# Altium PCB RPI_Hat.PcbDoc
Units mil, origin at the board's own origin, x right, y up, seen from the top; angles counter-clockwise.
Board outline 2247.25 x 3072.14 mil, 4 copper layers (Top Layer, Internal Plane 1, Internal Plane 2, Bottom Layer), stack 61.88 mil thick; 71 components, 40 nets, 316 pads, 202 vias.
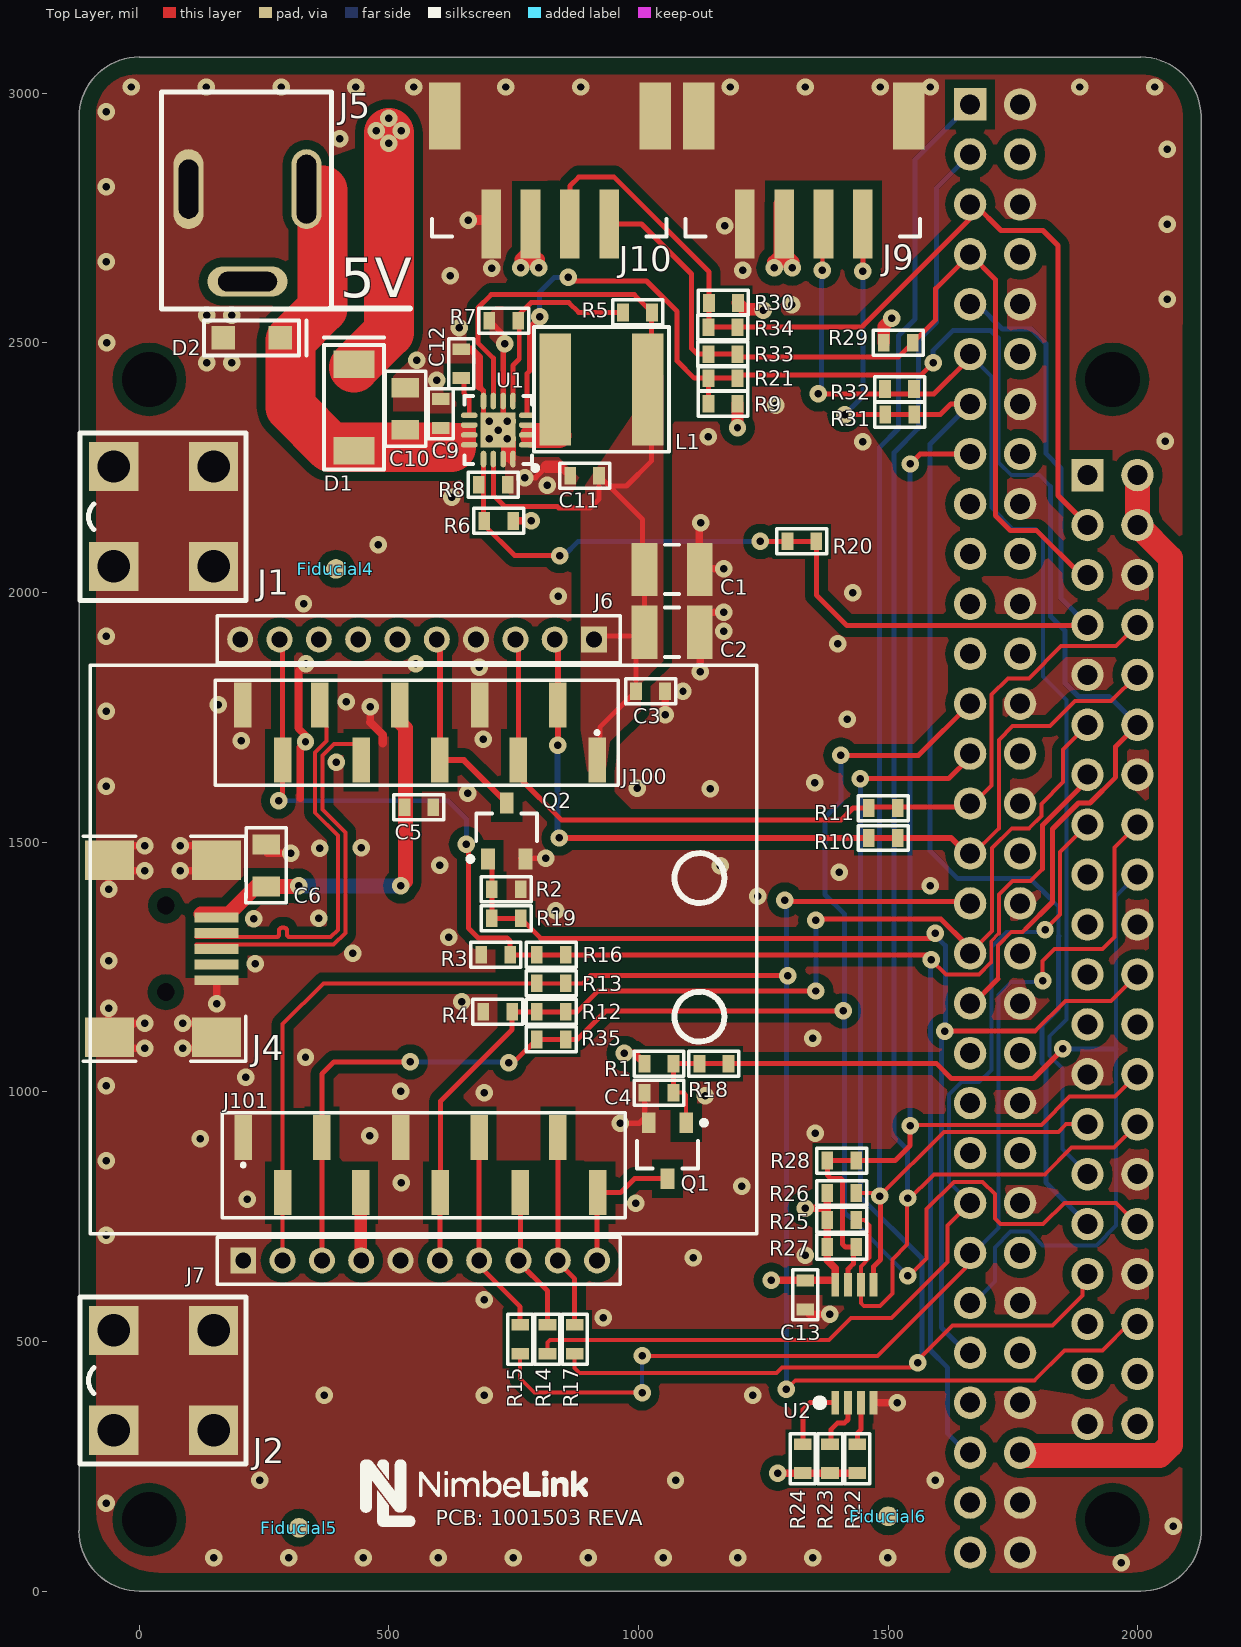
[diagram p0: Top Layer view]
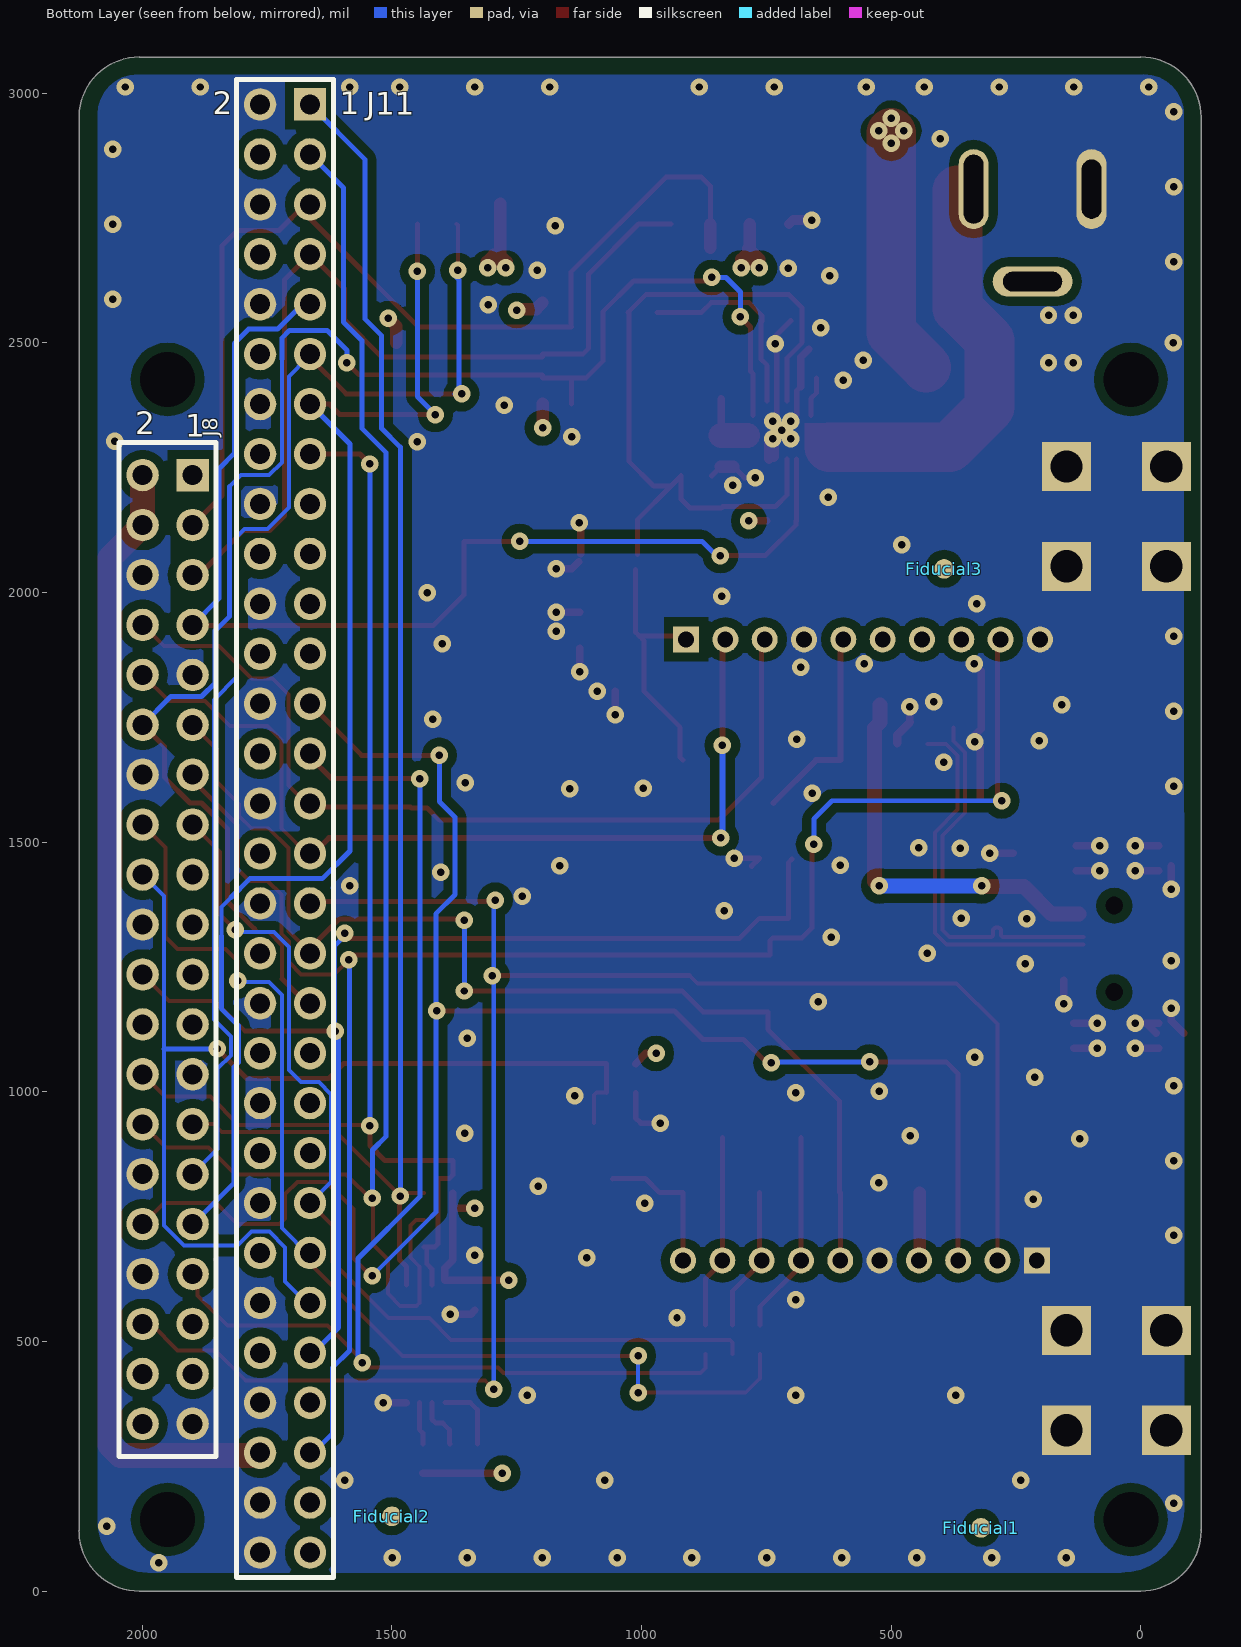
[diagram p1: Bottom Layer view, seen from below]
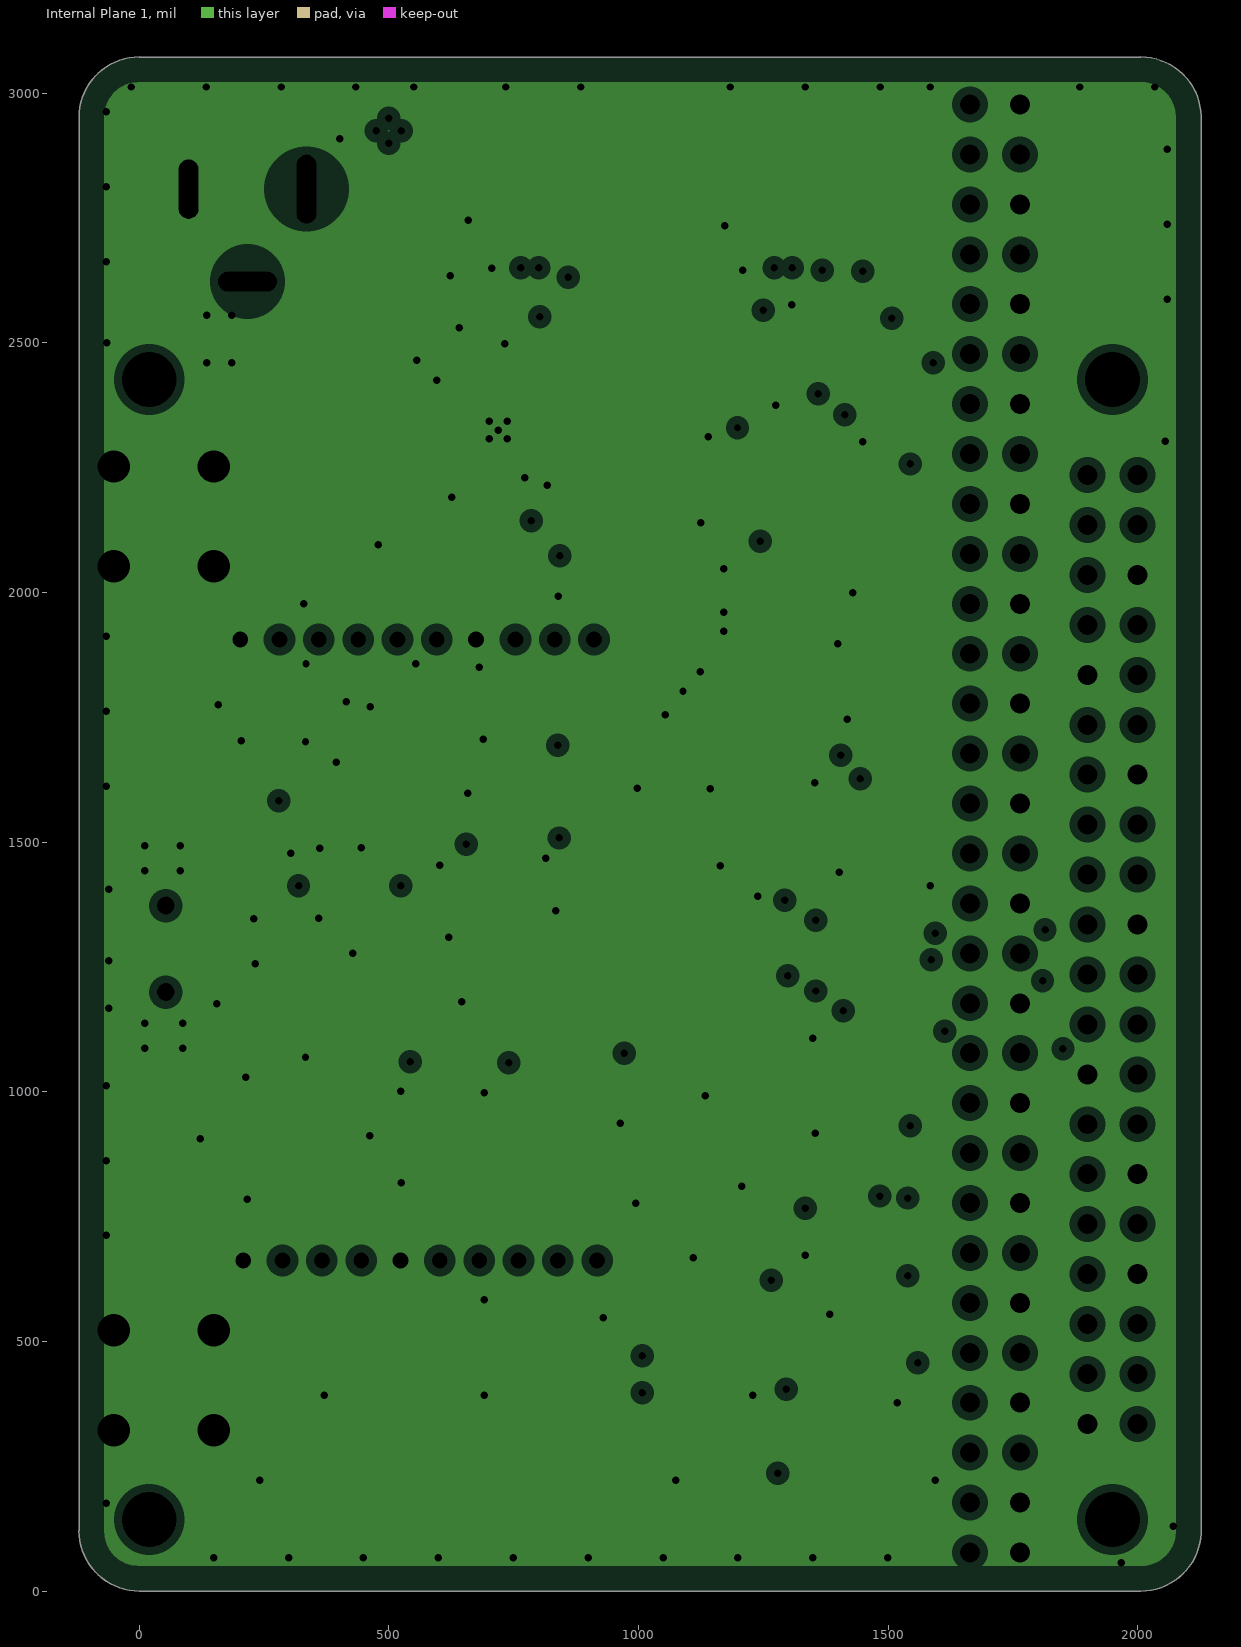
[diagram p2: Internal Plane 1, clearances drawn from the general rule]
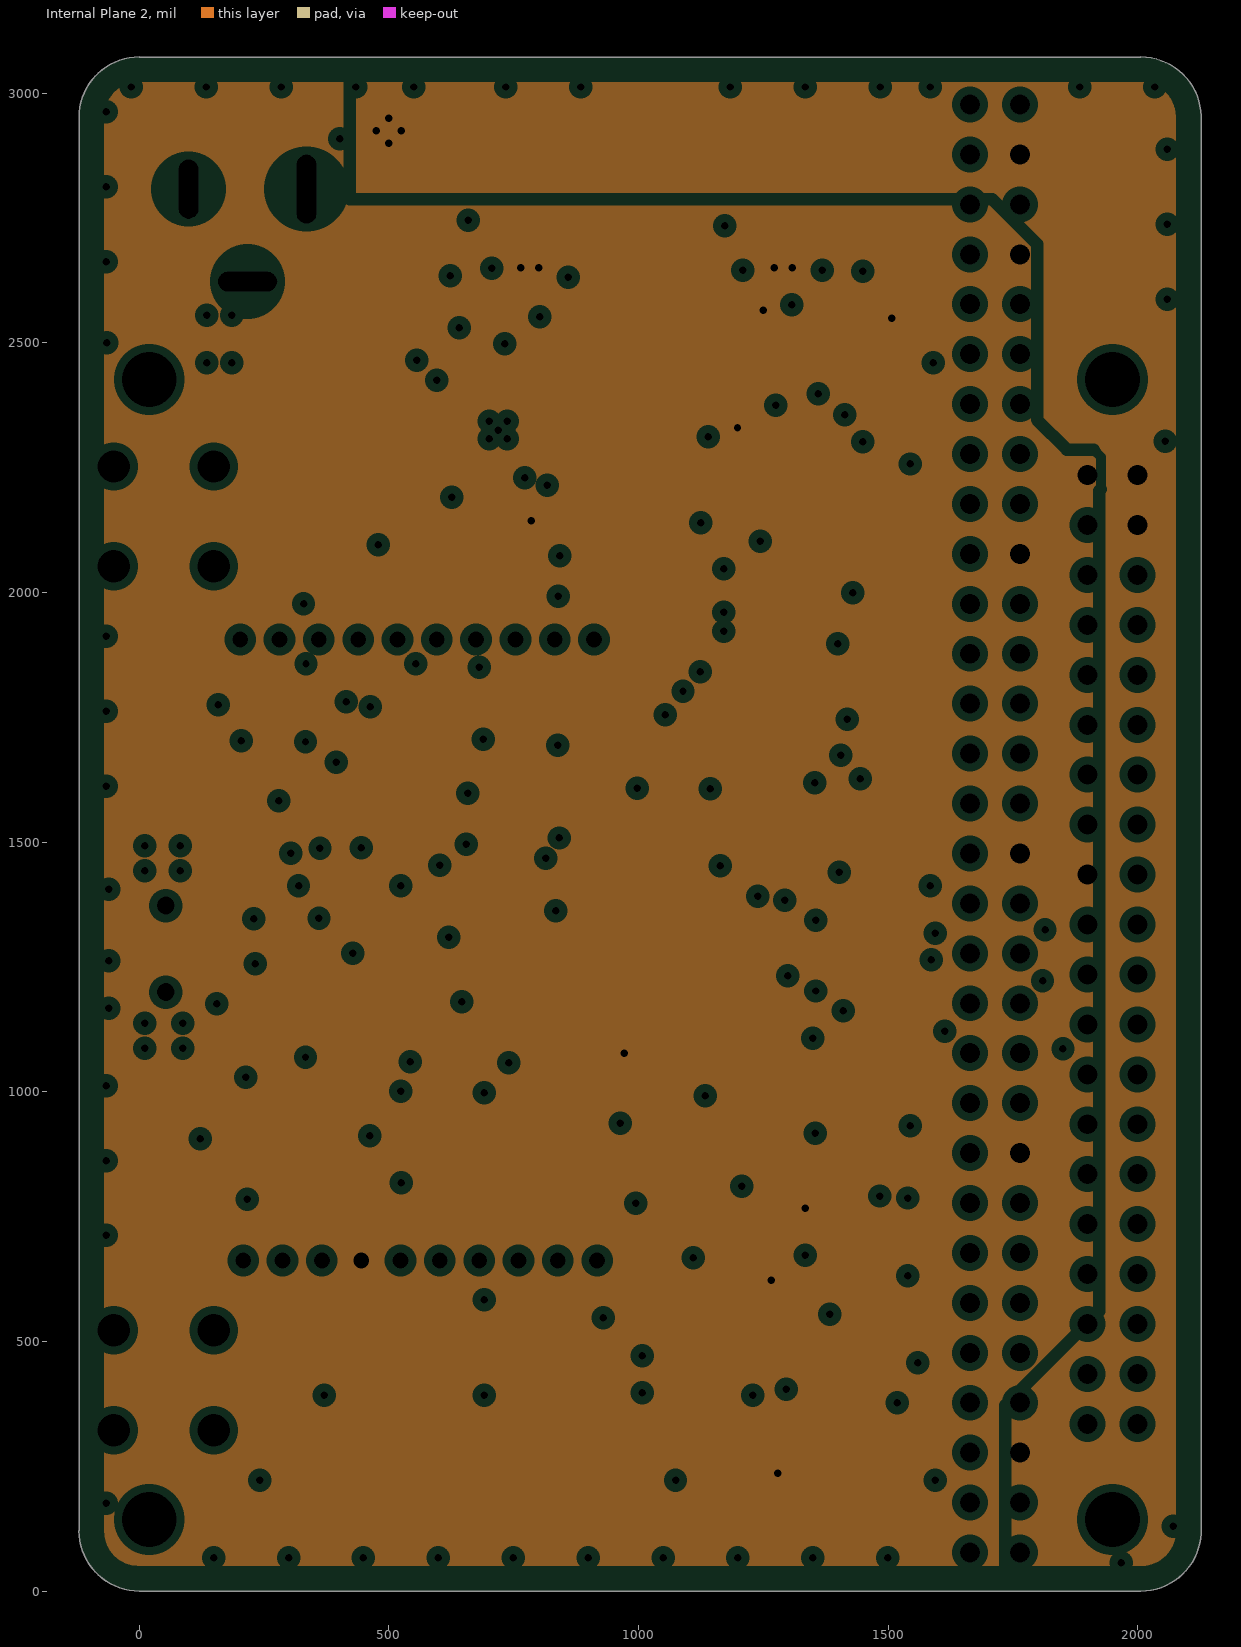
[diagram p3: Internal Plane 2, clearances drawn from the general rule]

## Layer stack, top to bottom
Top Solder: solder mask 0.4, Solder Resist, Dk 3.5
Top Layer: signal copper 1.37
Dielectric 1: core 6.7, FR-4, Dk 4.6
Internal Plane 1: plane copper 1.37, net GND
Dielectric 3: prepreg 43, Dk 4.6
Internal Plane 2: plane copper 1.37, net (Multiple Nets)
Dielectric 2: core 6.7, Dk 4.6
Bottom Layer: signal copper 1.37
Bottom Solder: solder mask 0.4, Solder Resist, Dk 3.5

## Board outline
-120.63,121 cw(c-118.11,121) -120.11,122.52 cw(c-118,123.89) -120.52,123.89 -120.52,2951.22 cw(c-118.09,2951.89) -120.61,2951.89 cw(c0.02,2951.89) 0.02,3072.51 cw(c0.02,3070) 0.76,3072.4 2005.15,3072.4 cw(c2005.89,3070) 2005.89,3072.51 cw(c2005.89,2951.89) 2126.49,2954.22 cw(c2124,2953.89) 2126.51,2953.89 2126.51,121.73 cw(c2124.11,121) 2126.63,121 cw(c2006,121) 2126.51,115.82 ccw(c2124,115.89) 2126.51,115.89 2126.51,115.82 cw(c2124,115.89) 2126.51,115.73 ccw(c2006,121) 2126.51,115.82 2126.51,115.73 cw(c2006,121) 2006,0.37 0,0.37 cw(c0,121)

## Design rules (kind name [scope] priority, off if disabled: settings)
Clearance Clearance_1 [InPolygon] p1: gap=18
Clearance [All] p2: gap=6
ComponentClearance "Skywire Model Clearance" [(HasFootprint('NPPN101BFCN-RC') OR (id='3D_STEP_Skywire'))] p1: gap=0 collisioncheckmode=3 verticalgap=0 showdistances=FALSE
ComponentClearance [All] p2: gap=7 collisioncheckmode=3 verticalgap=7 showdistances=FALSE
DiffPairsRouting [All] p1: maxlimit=30 minlimit=7 mostfreqgap=7 toplayer_minwidth=7 toplayer_maxwidth=100 toplayer_prefwidth=8 bottomlayer_minwidth=7 bottomlayer_maxwidth=100 bottomlayer_prefwidth=8 maxuncoupledlength=500
HoleSize [All] p1: absolutevalues=TRUE maxlimit=500 minlimit=15 maxpercent=80.000 minpercent=20.000
MinimumAnnularRing [All] p1: minimumring=10
MinimumSolderMaskSliver [All] p1: minsoldermaskwidth=0
PlaneClearance [All] p1: clearance=16
PlaneConnect [All] p1: planeconnectstyle=Direct reliefexpansion=20 reliefentries=4 reliefconductorwidth=20 reliefairgap=15
PolygonConnect "All Rule" [All] p1: connectstyle=Direct reliefconductorwidth=20 reliefentries=4 polygonreliefangle="90 Angle" airgapwidth=15
RoutingVias [All] p1: holewidth=15 width=35 viastyle="Through Hole" minholewidth=15 minwidth=35 maxholewidth=300 maxwidth=500
SilkToSilkClearance [All] p1: silktosilkclearance=0
SilkToSolderMaskClearance [IsPad] p1: minsilkscreentomaskgap=0 clearancetoexposedcopper=TRUE
SolderMaskExpansion SolderMaskExpansion_2 [isVia and TestpointBottom] p1: expansion=0
SolderMaskExpansion SolderMaskExpansion_1 [IsVia] p2: expansion=-10
SolderMaskExpansion [All] p3: expansion=0
UnpouredPolygon [All] p1: allowunpoured=FALSE
Width [All] p1: maxlimit=5000 minlimit=7 preferedwidth=10
21 further rules are at their usual default settings.

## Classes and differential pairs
component class TOP: C13 Fiducial1 Fiducial2 Fiducial3 Fiducial4 Fiducial5 Fiducial6 J8 J9 J10 J11 R10 R11 R12 R13 R14 R15 R16 R17 R18 R19 R20 R21 R22 R23 R24 R25 R26 R27 R28 R29 R30 R31 R32 R33 R34 R35 U2
component class Power: C9 C10 C11 C12 D1 D2 J5 L1 R5 R6 R7 R8 R9 U1
net class DIFF90: SKY_USB_N SKY_USB_P
component class Skywire: C1 C2 C3 C4 C5 C6 J1 J2 J4 J6 J7 J100 J101 Q1 Q2 R1 R2 R3 R4
differential pair SKY_USB: +SKY_USB_P -SKY_USB_N

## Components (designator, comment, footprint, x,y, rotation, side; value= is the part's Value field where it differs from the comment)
C1 "1001241" CAPC3225X25N_1210 1067,2046.42 r0 top
C2 "1001241" CAPC3225X25N_1210 1067,1920.42 r0 top
C3 "1000755" 0603 1024,1802.42 r0 top
C4 "1000755" 0603 1041,998.42 r180 top
C5 "1000755" 0603 560,1570 r0 top
C6 "1000780" 0805 254,1462.42 r90 top
C9 "1000755" 0603 604,2358.42 r90 top
C10 "1000780" 0805 533,2377 r90 top
C11 "C, 22 uF, 25V, 20%, X5R, 0603 CER" 0603 892,2234 r180 top
C12 "C, 470 pF, 50V, 5%, C0G/NP0, 0603 CER" 0603 645,2458.42 r270 top
C13 "1000755" 0603 1334,593.42 r270 top
D1 "1001261" SOD128 430,2371 r90 top
D2 "1000501" SOD123W 225,2510 r0 top
Fiducial1 "Fiducial" "Fiducial 1mm" 320,126.89 r0 bottom
Fiducial2 "Fiducial" "Fiducial 1mm" 1500,150 r0 bottom
Fiducial3 "Fiducial" "Fiducial 1mm" 394,2047.42 r90 bottom
Fiducial4 "Fiducial" "Fiducial 1mm" 394,2047.42 r90 top
Fiducial5 "Fiducial" "Fiducial 1mm" 320,126.89 r0 top
Fiducial6 "Fiducial" "Fiducial 1mm" 1500,150 r0 top
J1 "UFL to SMA" "UFL TO SMA" -51,2252.42 r270 top
J2 "UFL to SMA" "UFL TO SMA" -51,522.42 r270 top
J4 "USB MINI B" 10033526-N3212LF -177,1286.42 r270 top
J5 "1000221" PJ-202A 335,2807.89 r180 top
J6 "1000864" NPPN101BFCN-RC 910.85,1906 r270 top
J7 "1000864" NPPN101BFCN-RC 208.34,662.42 r90 top
J8 "1001252" PPPC202LFBN-RC 1899.13,2235.16 r0 bottom locked
J9 "1001260" S4B-PH-SM4-TB(LF)(SN) 1449,2738 r0 top
J10 "1001260" S4B-PH-SM4-TB(LF)(SN) 941,2738 r0 top
J11 "1001253" PPPC302LFBN-RC 1664,2977.42 r0 bottom locked
J100 "1000865" NPPN101BFLC-RC 917,1719.42 r270 top locked
J101 "1000865" NPPN101BFLC-RC 208.34,853.28 r90 top locked
L1 "1001263" NR6028 926,2407 r0 top
Q1 "1000512" SOT95P300X115-3N 1058,882 r270 top
Q2 "1000512" SOT95P300X115-3N 736,1522.42 r90 top
R1 "100K" 0603 1041,1056.42 r180 top
R2 "10K" 0603 735,1405.89 r180 top
R3 "#NAME?" 0603 714,1274.42 r0 top
R4 "#NAME?" 0603 718,1160.42 r0 top
R5 "715K" 0603 998,2561 r0 top
R6 "100K" 0603 720,2143.42 r0 top
R7 "1001234" 0603 730,2544.42 r0 top
R8 "100K" 0603 709,2216 r180 top
R9 "100K" 0603 1169.16,2378 r0 top
R10 "0" 0603 1490,1508.42 r180 top
R11 "0" 0603 1490,1568.42 r0 top
R12 "0" 0603 825,1160.42 r180 top
R13 "0" 0603 825,1217.42 r180 top
R14 "0" 0603 817.5,504.42 r270 top
R15 "0" 0603 763,504.42 r270 top
R16 "0" 0603 825,1274.42 r180 top
R17 "0" 0603 872,504.42 r270 top
R18 "0" 0603 1151,1056.42 r180 top
R19 "0" 0603 735,1347.42 r180 top
R20 "0" 0603 1327,2102.42 r180 top
R21 "0" 0603 1169.16,2429.42 r0 top
R22 "#NAME?" 0603 1438,265.42 r270 top
R23 "#NAME?" 0603 1383.5,265.42 r270 top
R24 "#NAME?" 0603 1329,265.42 r270 top
R25 "1000803" 0603 1407,743.42 r180 top
R26 "1000803" 0603 1407,797.42 r180 top
R27 "#NAME?" 0603 1407,689.42 r180 top
R28 "0" 0603 1407,862.42 r0 top
R29 "1000803" 0603 1520,2500 r180 top
R30 "1000803" 0603 1170,2580 r0 top
R31 "0" 0603 1523,2356.42 r0 top
R32 "0" 0603 1522.84,2407.44 r0 top
R33 "0" 0603 1169,2477.42 r180 top
R34 "0" 0603 1169,2531.42 r180 top
R35 "0" 0603 825,1105 r180 top
U1 "TPS62130RGTT" QFN50P300X300X100_HS-17N 719,2325.42 r180 top
U2 "." "TSSOP8 4.4x3 CASE 948AL-01" 1394,377.42 r90 top

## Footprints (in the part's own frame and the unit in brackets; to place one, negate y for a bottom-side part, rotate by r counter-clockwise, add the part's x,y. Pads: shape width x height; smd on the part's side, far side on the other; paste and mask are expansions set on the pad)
0603 [mm]
  rect 0.6x0.9 smd: 1(-0.737,0) 2(0.737,0)
  silkscreen extent -1.27,-0.64 1.27,0.64, body extent -0.8,-0.38 0.8,0.42, height 0.45
0805 [mm]
  rect 1x1.4 smd: 1(-1.3,0) 2(0.838,0)
  silkscreen extent -2.12,-1.03 1.69,1.02, body extent -1.21,-0.6 0.79,0.65, height 0.5
10033526-N3212LF [mm]
  rect 0x0 hole 0.9 unplated: 0(-2.2,5.85) 0(2.2,5.85)
  rect 0.5x2.25 smd: 1(-1.6,8.43) 2(-0.8,8.43) 3(0,8.43) 4(0.8,8.43) 5(1.6,8.43)
  rect 2x2.5 smd: 6(-4.5,8.43) 6(-4.5,2.98) 6(4.5,8.43) 6(4.5,2.98)
  silkscreen extent -5.72,1.65 5.71,9.91, body extent -4.95,0 4.95,9.4, height 4.05
CAPC3225X25N_1210 [mm] "Chip Capacitor, 2-Leads, 1210"
  rect 1.3x2.7 smd: 1(-1.4,0) 2(1.4,0)
  silkscreen extent -0.35,-1.25 0.35,1.25, body extent -1.7,-1.35 1.7,1.35, height 2.5
"Fiducial 1mm" [mm]
  round 1 smd paste-0.5: Fiducial(0,0)
NPPN101BFCN-RC [mil]
  rect 52x52 hole 31.5: 1(0,0)
  round 52 hole 31.5: 2(0,-78.74) 3(0,-157.48) 4(0,-236.22) 5(0,-314.96) 6(0,-393.7) 7(0,-472.44) 8(0,-551.18) 9(0,-629.92) 10(0,-708.66)
  silkscreen extent -48,-755 47,52
NPPN101BFLC-RC [mm] "Skywire Footprint with surfacemount pads"
  rect 2.29x0.89 smd: 1(1.4,0) 2(-1.4,-2) 3(1.4,-4) 4(-1.4,-5.969) 5(1.4,-8) 6(-1.4,-10.033) 7(1.4,-12) 8(-1.4,-14.097) 9(1.4,-16) 10(-1.4,-18.034)
  silkscreen extent -2.67,-19.43 2.67,1.07, body extent -2.14,-19.43 2.31,1.07, height 4.5
NR6028 [mm]
  rect 1.6x5.7 smd: 1(-2.35,0) 2(2.35,0)
  silkscreen extent -3.43,-3.17 3.43,3.17, body extent -3.05,-3.05 3.05,3.05, height 2.8
PJ-202A [mil] "PJ-202A  Barrel Plug"
  oval 60x160 hole 39.37 slot 137.8 at 90 deg: 1(0,0)
  oval 160x60 hole 39.37 slot 118.11 at 0 deg: 2(118.11,185.04)
  oval 60x160 hole 39.37 slot 118.11 at 90 deg: 3(236.22,0)
  silkscreen extent -50,-195 290,240, body extent -28,-180 538,190, height 433
PPPC202LFBN-RC [mil]
  rect 65x65 hole 40: 1(0,0)
  round 65 hole 40: 2(100,0) 3(0,100) 4(100,100) 5(0,200) 6(100,200) 7(0,300) 8(100,300) 9(0,400) 10(100,400) 11(0,500) 12(100,500) 13(0,600) 14(100,600) 15(0,700) 16(100,700) 17(0,800) 18(100,800) 19(0,900) 20(100,900) 21(0,1000) 22(100,1000) 23(0,1100) 24(100,1100) 25(0,1200) 26(100,1200) 27(0,1300) 28(100,1300) 29(0,1400) 30(100,1400) 31(0,1500) 32(100,1500) 33(0,1600) 34(100,1600) 35(0,1700) 36(100,1700) 37(0,1800) 38(100,1800) 39(0,1900) 40(100,1900)
  silkscreen extent -47,-65 147,1965, body extent -51,-60 149,1960, height 335
PPPC302LFBN-RC [mil]
  rect 65x65 hole 40: 1(0,0)
  round 65 hole 40: 2(100,0) 3(0,100) 4(100,100) 5(0,200) 6(100,200) 7(0,300) 8(100,300) 9(0,400) 10(100,400) 11(0,500) 12(100,500) 13(0,600) 14(100,600) 15(0,700) 16(100,700) 17(0,800) 18(100,800) 19(0,900) 20(100,900) 21(0,1000) 22(100,1000) 23(0,1100) 24(100,1100) 25(0,1200) 26(100,1200) 27(0,1300) 28(100,1300) 29(0,1400) 30(100,1400) 31(0,1500) 32(100,1500) 33(0,1600) 34(100,1600) 35(0,1700) 36(100,1700) 37(0,1800) 38(100,1800) 39(0,1900) 40(100,1900) 41(0,2000) 42(100,2000) 43(0,2100) 44(100,2100) 45(0,2200) 46(100,2200) 47(0,2300) 48(100,2300) 49(0,2400) 50(100,2400) 51(0,2500) 52(100,2500) 53(0,2600) 54(100,2600) 55(0,2700) 56(100,2700) 57(0,2800) 58(100,2800) 59(0,2900) 60(100,2900)
  silkscreen extent -47,-50 147,2950, body extent -50,-60 150,2960, height 335
QFN50P300X300X100_HS-17N [mm] "QFN, 16-Leads, Body 3.00x3.00mm, Pitch 0.50mm, Thermal Pad 1.78x1.78mm, IPC Medium Density"
  oval 0.85x0.28 smd: 1(-1.475,0.75) 2(-1.475,0.25) 3(-1.475,-0.25) 4(-1.475,-0.75) 9(1.475,-0.75) 10(1.475,-0.25) 11(1.475,0.25) 12(1.475,0.75)
  oval 0.28x0.85 smd: 5(-0.75,-1.475) 6(-0.25,-1.475) 7(0.25,-1.475) 8(0.75,-1.475) 13(0.75,1.475) 14(0.25,1.475) 15(-0.25,1.475) 16(-0.75,1.475)
  rect 1.78x1.78 smd paste-0.8: 17(0,0)
  silkscreen extent -2,-1.73 1.73,2.06, body extent -1.58,-1.57 1.57,1.58, height 1
S4B-PH-SM4-TB(LF)(SN) [mm]
  rect 1x3.5 smd: 1(-6,0) 2(-4,0) 3(-2,0) 4(0,0)
  rect 1.6x3.4 smd: 5(-8.35,5.5) 5(2.35,5.5)
  silkscreen extent -9.02,-0.64 2.92,0.25, body extent -9,-1.52 2.9,7.08, height 5.6
SOD123W [mm]
  rect 1.2x1.2 smd: A(-1.45,0) K(1.45,0)
  silkscreen extent -2.41,-0.89 2.79,0.89, body extent -1.4,-0.95 1.4,0.95, height 2.5
SOD128 [mm]
  rect 1.4x2.1 smd: A(-2.2,0) K(2.2,0)
  silkscreen extent -3.17,-1.52 3.56,1.52, body extent -2.03,-1.33 1.91,1.4, height 2.5
SOT95P300X115-3N [mm] "SOT23, 3-Leads, Body 3.10x3.00mm, Pitch 0.95mm, IPC Medium Density"
  rect 1.05x0.7 smd: 1(-1.425,0.95) 2(-1.425,-0.95) 3(1.425,0)
  silkscreen extent -1.55,-1.55 0.9,1.98, body extent -0.9,-1.55 0.9,1.55, height 1.15
"TSSOP8 4.4x3 CASE 948AL-01" [mm]
  rect 1.2x0.4 smd: 1(0,0) 2(0,-0.65) 3(0,-1.3) 4(0,-1.95) 5(6,-1.95) 6(6,-1.3) 7(6,-0.65) 8(6,0)
  silkscreen extent -0.05,0.74 0.05,0.84, body extent -0.35,-2.46 6.25,0.59, height 1.2
"UFL TO SMA" [mm]
  rect 2.5x2.5 hole 1.651: 1(0,5.08) 1(0,0) 1(5.08,5.08) 1(5.08,0)
  silkscreen extent -1.7,-1.71 6.81,6.73, body extent -1.02,-10.03 5.97,22.61, height 9.44

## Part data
C1 C2: "Capacitor. 100uF, 10V, 20%, X5R, 1210"
C3 C4 C5 C9 C13: "Capacitor, 0.1 uF, 16V, 5%, X7R, 0603"
C6 C10: "Capacitor, 10 uF, 25V, 10%, X5R, 0805"
C11: library part 1000932, "Capacitor, 22 uF, 25V, 20%, X5R, 0603"
C12: library part 1000777, "Capacitor, 470 pF, 50V, 5%, C0G/NP0, 0603"
D1: "Diode, Schottky, 30V, 3A, 0.360 Vf, SOD-128"
D2: "Diode, TVS, Unidirectional, 5V, 43.5A, SOD-123W"
Fiducial1 Fiducial2 Fiducial3 Fiducial4 Fiducial5 Fiducial6: "Fiducial, 1mm"
J1 J2: library part 1000732, "Connector, ANT, UFL to PCB Mount SMA, UFL Down, 53mm, TH"
J4: library part 1000127, "Connector, USB, Mini B, Right Angle, SMD"
J5: "Connector, Barrel, 24V, 2.5A, 2.1mm ID, 5.5mm OD"
J6 J7: "Connector, Header, Female, 2.00mm, 10x1, TH"
J8: "Connector, Header, Female, 2.54mm, 20x2, TH"
J9 J10: "Connector, Header, Male, 2.00mm, 4x1, Right Angle, SMD"
J11: "Connector, Header, Female, 2.54mm, 30x2, TH"
J100 J101: "Connector, Female, 2.00mm, 10x1, SMD, Left Oriented"
L1: "Inductor, 2.2uH, 3.7A, 30%, 26mOhm, 6.00x6.00mm"
Q1 Q2: "Transistor, MOSFET, N-CH, 25V, 0.220mA, SOT-23-3"
R1 R6 R8 R9: library part 1000799, "Resistor, 100K, 1%, 1/10W, 0603"
R2: library part 1000591, "Resistor, 10K, 1%, 1/10W, 0603"
R3 R4 R22 R23 R24 R27: library part 1000590, "Resistor, 1K, 1%, 1/10W, 0603"
R5: library part 1000656, "Resistor, 715K, 1%, 1/10W, 0603"
R7: "Resistor, 180K, 1%, 1/10W, 0603"
R10 R11 R12 R13 R14 R15 R16 R17 R18 R19 R20 R21 R28 R31 R32 R33 R34 R35: library part 1000666, "Resistor, 0, 1/10W, 0603"
R25 R26 R29 R30: "Resistor, 4.7K, 1%, 1/10W, 0603"
U1: library part 1001036, "IC, Buck, ADJ, 3V-17V , 3A, QFN"
U2: library part 1001385, "IC, EEPROM, I2C, 32Kb, 400KHz, 1.7V-5.5V, 8-TSSOP"

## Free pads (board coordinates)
  round 0 hole 110 unplated: 0(20,143.42) 0(20,2426.89) 0(1949.13,143.42) 0(1949.13,2426.89)
  rect 20x20 on Mech1: 0(1899.13,2235.16)
  round 50 on Mech1: 1(1999.13,2235.16)
  round 50 on Drill Drawing: 1(1999.13,2235.16)

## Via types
v1: diameter 35, hole 15, Top Layer to Bottom Layer, 202 vias

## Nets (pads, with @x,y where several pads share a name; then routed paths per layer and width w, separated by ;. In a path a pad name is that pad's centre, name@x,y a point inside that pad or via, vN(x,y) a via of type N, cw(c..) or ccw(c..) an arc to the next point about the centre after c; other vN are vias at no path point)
EEPROM_SCL: J8.28 J11.3 R25.1 U2.6 | length 3156.9
  Top Layer w8: R25.1 1452,743.42 1463,732.42 1463,668.42 1445.18,650.61 U2.6 1445.18,577.24 1451,571.42 1483.63,571.42 1508.1,595.9 1508.1,664.1 1538,694 1538,781.42 1591.5,834.92 1813.5,834.92 1867,888.42 1952.4,888.42 J8.28
  Bottom Layer w10: v1(1539,787.42) 1539,883.5 1511.5,911 1511.5,2280 1560.25,2328.75 1560.25,2504.75 1597,2541.5 1597,2810.42 J11.3
EEPROM_SDA: J8.27 J11.1 R26.1 U2.5 | length 2968.5
  Top Layer w8: R26.1 1470,797.42 v1@1485,782.42 ; v1(1483,791.42) 1611.5,919.92 1840.72,919.92 1855.95,935.16 J8.27
  Top Layer w10: U2.5 1470.77,650.2 1485,664.42 v1@1485,782.42
  Bottom Layer w10: v1@1483,789.42 v1(1483,791.42) 1483,2291 1520.5,2328.5 1520.5,2514.5 1553.5,2547.5 1553.5,2866.92 J11.1
GND: C1.2 C2.2 C3.2 C4.2 C5.2 C6.2 C9.2 C10.2 C11.2 C12.1 C13.2 D2.A J1.1 J2.1 J4.5 J4.6 J5.3 J6.4 J6.10 J7.1 J7.5 J8.6 J8.9 J8.14 J8.20 J8.25 J8.30 J8.34 J8.39 J9.1 J9.5 J10.1 J10.5 J11.2 J11.6 J11.10 J11.14 J11.18 J11.22 J11.26 J11.30 J11.34 J11.38 J11.42 J11.46 J11.50 J11.54 J11.58 J11.60 J100.4 J100.10 J101.1 J101.5 Q1.2 Q2.2 R2.1 R3.1 R4.1 R7.1 R8.1 U1.6 U1.8 U1.15 U1.16 U1.17 U2.4 | length 2095.1
  Top Layer w11: 681.22,2412.21 689.47,2403.95 U1.8 U1.17@689.47,2354.95 ; R7.1 728.84,2516.58 U1.6 U1.17@728.84,2343.42 ; v1(772,2230) 794,2230 816,2252 ; Q2.2@779.4,1452.29 764.27,1467.42 v1(814,1467.42) ; 841,2252 C11.2@859,2234 ; v1(963,937.42) 1001.5,937.42 1012,947.93 C4.2
  Top Layer w15: J4.6@-86,1117.42 -61,1142.42 v1(-61,1167.42) ; v1(-61,1405.42) J4.6@-61,1452.42 ; J4.6@-36,1087.42 v1(11,1087.42) ; J4.6@-36,1137.42 v1(11,1137.42) ; J4.6@-36,1442.42 v1(11,1442.42) ; J4.6@-36,1492.42 v1(11,1492.42) ; J4.6@-31,1117.42 J4.6@-11,1137.42 ; v1(82,1442.42) J4.6@129,1442.42 ; v1(82,1492.42) J4.6@129,1492.42 ; v1(87,1087.42) J4.6@134,1087.42 ; v1(87,1137.42) J4.6@134,1137.42 ; v1(154.89,1176.43) J4.5 ; C6.2@256,1477.42 v1(303,1477.42) ; 322,1588 322,1690 v1(333,1701) 333,1713.86 319.48,1727.38 319.48,1842.9 v1(334,1857.42) ; 463,1740 v1(463,1771) ; 665,2487.42 681.22,2471.21 681.22,2412.21 ; v1(1053,1755.42) C3.2 ; C1.2@1122,2077.42 v1@1122,2124.42 ; v1(1124,1841.42) C2.2@1124,1888.42 ; C2.2@1124,1960.42 v1(1171,1960.42) ; C1.2@1126,2061.42 1140,2047.42 v1@1174,2047.42 ; C13.2@1334,562.42 1341.42,555 v1(1383,555) ; U2.4 v1(1517.77,377.42)
  Top Layer w17: 463,1740 488,1715 488,1698
  Top Layer w20: v1(659,2746) 696.78,2746 J10.1 ; v1(719,2325.42) U1.17@737,2307.42 ; U1.15@734.34,2271.54 U1.17@734.34,2300.09 ; U1.17@736,2304.42 740,2304.42 744.34,2300.09 U1.16@744.34,2267.35
  Top Layer w25: 816,2252 841,2252
  other v1: 1967,57.42 149,67.42 299,67.42 449,67.42 599,67.42 749,67.42 899,67.42 1049,67.42 1199,67.42 1349,67.42 1499,67.42 2071,130.42 -66,176.42 241,222.42 1074,222.42 1594,222.42 371,392.42 691,392.42 1229,392.42 929,547.42 691,584 1110,668 1334,672.42 -66,712.42 994,777 216,785 1207,811.42 525,818 -66,862.42 122,906 462,912 1354,917.42 1134,992.42 691,998 524,1001 -66,1012.42 213,1029 333,1069 1349,1107 646,1180.42 232,1257 -61,1262.42 428,1278 620,1310 229,1347 360,1348 834,1362.42 1239,1392 1584,1412.42 1402,1440 1164,1452.42 602,1454 362,1488 445,1489 658,1598 1144,1607.42 997,1608 -66,1612.42 1353,1619 395,1660 204,1703 689,1706 1418,1746 -66,1762.42 158,1775 415,1781 1089,1802.42 681,1850 554,1857.42 1399,1897 -66,1912.42 1171,1922.42 329,1977.42 839,1992.42 1429,2000 1171,2047.42 479,2096 1125,2140 626,2191 817,2215 1449,2302.42 2055,2303 701,2307.92 737,2307.92 1140,2312 701.16,2343.26 737,2343.42 1275,2375 596,2425 135,2460 185,2460 556,2465 732,2498 -65,2500.42 641,2530 135,2555 185,2555 1307,2576 2059,2587.42 623,2634 1209,2645 706,2649 -66,2662.42 1173,2735 2059,2737.42 -66,2812.42 2059,2887.42 402,2909 -66,2962.42 -16,3012.42 134,3012.42 284,3012.42 434,3012.42 550,3012.42 734,3012.42 884,3012.42 1184,3012.42 1334,3012.42 1484,3012.42 1584,3012.42 1884,3012.42 2034,3012.42
GPIO4: J8.7 J11.9 R6.1 R8.2 R20.1 R20.2 U1.13 | length 2293.9
  Top Layer w10: R6.1@689.47,2143.42 U1.13 ; R6.1 691,2135 752,2074 v1(842,2074) ; v1(1244,2102.42) R20.2 R20.1 1356,1995 1417.08,1933.92 1899.13,1933.92 J8.7
  Bottom Layer w10: v1(842,2074) 850.58,2074 879,2102.42 v1(1244,2102.42) ; J11.9 1679,2577.42 1729,2527.42 1787,2527.42 1815.63,2498.79 1815.63,2278.84 1846,2248.47 1846,1988.29 J8.7
GPIO5: J8.29 J9.3 J11.11 R32.1 R32.2 | length 2487.5
  Top Layer w8: v1(1368,2645) 1368,2735.74 J9.3
  Top Layer w10: v1(1360,2398) 1591.58,2398 J11.11@1664,2470.42
  Bottom Layer w8: J11.11 1669.71,2471.71 1669.71,2469.5 1706.5,2432.71 1706.5,2169.92 1749,2127.42 1795,2127.42 1810,2112.42 1810,1831.42 1856.63,1784.79 1856.63,1144.63 1822.5,1110.5 1822.5,1073 1849,1046.5 1849,885.29 J8.29
  Bottom Layer w10: v1(1360,2398) 1374,2398 1366,2406 1366,2627 v1@1379,2640
GPIO6: J8.31 J9.4 J11.13 R31.1 R31.2 | length 2575.4
  Top Layer w10: v1(1413,2356.42) R31.1 R31.2 1604.42,2356.42 1625.42,2377.42 J11.13 ; v1(1449,2643) J9.4
  Bottom Layer w8: 1822.21,1389.21 1841.5,1369.92 1841.5,1312.19
  Bottom Layer w10: v1(1413,2356.42) 1449,2392.42 v1(1449,2643) ; J11.13 1584,2297.42 1584,1482.42 1639.5,1426.92 1784.5,1426.92 1822.21,1389.21 ; 1841.63,1312.33 1841.5,1312.19 1841.5,1166.5 1807.5,1132.5 1807.5,1058.4 1816,1049.9 1816,818.29 J8.31
GPIO7: J8.26 J11.15 R27.1 R28.1 R28.2 U2.7 | length 2474.1
  Top Layer w8: v1(1544,932.42) 1545.5,933.92 1807,933.92 1863.5,990.42 1954.4,990.42 J8.26
  Top Layer w10: U2.7 1419.59,645.01 1430.18,655.61 R27.1@1430.18,689.42 ; R27.1 R27.1@1430.18,689.42 ; v1(1544,932.42) 1544,892.42 1514,862.42 R28.2 R28.1 1378,833.42 1385.28,826.14 1405.28,826.14 1408,823.42 1408,695.42 1414,689.42 R27.1@1430.18,689.42 ; v1(1544,2257.42) 1564,2277.42 1657,2277.42 J11.15@1664,2270.42
  Bottom Layer w10: v1(1544,932.42) v1(1544,2257.42)
GPIO12: J7.3 J8.32 J11.25 J101.3 R35.1 R35.2 | length 3599.5
  Top Layer w8: v1@1533,634 1545,634 1577,666 1577,765 1631.92,819.92 1689.08,819.92 1714,795 1714,746 1725.08,734.92 1809.92,734.92 1852.66,777.66 1956.63,777.66 J8.32
  Top Layer w10: J7.3@365.82,659.42 365.82,821 J101.3 365.82,1035.82 390,1060 v1(543,1060) ; v1(740,1058) 749,1058 R35.2 R35.1 877,1105 934,1162 v1(1410,1162) ; v1(1405,1674) 1560.58,1674 J11.25
  Bottom Layer w8: 1420,751 v1(1539,632)
  Bottom Layer w10: v1(543,1060) v1@740,1060 ; v1(1405,1674) 1405,1581.5 1373.5,1550 1373.5,1395.03 1412,1356.53 1412,759 1420,751
GPIO13: J8.33 J11.27 R17.2 | length 2623.2
  Top Layer w8: R17.2 872,447.42 882,437.42 1276.42,437.42 1287.42,448.42 1545,448.42 1629,532.42 1829,532.42 1889,592.42 1889,625.02 J8.33
  Top Layer w10: v1(1444,1627.42) 1621,1627.42 J11.27@1664,1670.42
  Bottom Layer w10: v1(1444,1627.42) 1444,790.12 1568,666.12 1568,466.42 v1(1559,457.42)
GPIO18: J8.12 J11.37 R9.1 R21.1 R21.2 U1.4 | length 3134
  Top Layer w8: 1720,1226.42 1720,1293.53 1746.4,1319.92 1768.62,1319.92 1775.62,1326.92
  Top Layer w10: U1.4 777.07,2439 781.81,2443.74 781.81,2531.81 v1(802,2552) ; v1(859,2631) 866,2624 1016,2624 1077,2563 1077,2464 1111.58,2429.42 R21.1 ; R9.1 R21.1 ; v1(1590,2460) 1566.15,2436.15 1471.26,2436.15 1471.03,2435.92 1198.16,2435.92 R21.2 R21.1 ; J11.37@1664,1170.42 1720,1226.42 ; 1775.62,1326.92 1829,1380.3 1829,1526.54 1881.12,1578.66 1904.15,1578.66 1955.63,1630.14 1955.63,1691.66 J8.12
  Bottom Layer w8: 1720.5,2468 1720.5,2260.82 1746.4,2234.92 1802.5,2234.92 1825,2212.42
  Bottom Layer w10: v1(802,2552) 802,2602 831,2631 v1(859,2631) ; v1(1590,2460) 1590,2485 1630,2525 1705,2525 1720.5,2509.5 1720.5,2468 ; 1825,2212.42 1825,1952.49 1854,1923.49 1854,1818.77 1881.12,1791.66 1942.63,1791.66 J8.12
GPIO22: J8.15 J11.45 R14.2 | length 1977.9
  Top Layer w8: R14.2 817.5,497.92 823,503.42 1381.42,503.42 1425,547 1507,547 1619,659 1619,732.42 J11.45 ; v1(1814,1325) 1844,1355 1844,1480.02 J8.15
  Bottom Layer w8: J11.45@1664,770.42 J11.45@1667.5,773.92 ; J11.45 1621.5,819.92 1621.5,995.03 1646.4,1019.92 1682.2,1019.92 1706.5,1044.22 1706.5,1289.92 1736.5,1319.92 v1@1807.5,1319.92
GPIO23: J8.16 J11.47 R15.2 | length 2221.8
  Top Layer w8: R15.2 763,426.42 792,397.42 v1(1007,397.42) ; v1(1007,471.42) 1478.8,471.42 1664,656.63 J11.47@1664,670.42 ; v1(1809,1222.42) 1809,1262.42 1832.79,1286.21 1929.21,1286.21 1953.49,1310.49 1953.49,1489.51 J8.16
  Bottom Layer w8: v1(1007,397.42) v1(1007,471.42) ; J11.47@1664,670.42 1720.5,726.92 1720.5,1194.03 1746.4,1219.92 1806.5,1219.92 v1(1809,1222.42)
GPIO24: C4.1 J8.18 J11.49 Q1.1 R1.1 R18.1 R18.2 | length 2206.8
  Top Layer w8: C4.1 1090.58,998.42 1095.4,993.6 Q1.1
  Top Layer w10: C4.1 R1.1 R18.2 R18.1 1597,1056.42 1626.5,1026.92 1790.92,1026.92 v1(1850,1086)
  Bottom Layer w8: J11.49@1664,570.42 1714,620.42 1714,688.74 1745.19,719.92 1781.6,719.92 1808.87,692.66 1916.74,692.66 1956.63,732.55 1956.63,1086 1956.63,1392.66 J8.18
  Bottom Layer w10: v1(1850,1086) 1956.63,1086
GPIO25: J8.22 J11.51 Q2.1 R2.2 R19.1 R19.2 | length 2341.3
  Top Layer w8: 1794,1121.42 1855,1182.42 1946.4,1182.42 J8.22
  Top Layer w10: Q2.1 706,1458.92 R2.2 R19.2 R19.1 804,1307.42 1585,1307.42 v1@1591,1313.42 ; v1(1613,1121.42) 1794,1121.42
  Bottom Layer w10: v1(1594,1317.42) 1594,1313.42 1614.5,1292.92 v1@1614.5,1121.42 ; v1(1613,1121.42) 1606.5,1114.92 1606.5,527.92 J11.51@1664,470.42
GPIO27: J6.9 J8.13 J11.55 J100.9 R3.2 R16.1 R16.2 | length 3556.3
  Top Layer w7: 1705.34,1258.71 1706,1259.37 1706,1302 1721.5,1317.5
  Top Layer w8: v1(1586,1264.42) 1615.5,1234.92 1681.6,1234.92 1705.34,1258.66 ; 1721.5,1317.5 1721.5,1395.03 1748.9,1422.42 1785,1422.42 1809,1446.42
  Top Layer w10: v1@287.08,1583 J6.9@287.08,1913.42 ; v1@659,1496 659,1328 679,1308 737,1308 743,1302 R3.2 R16.2 R16.1 1576,1274.42 v1(1586,1264.42) ; 1809,1446.42 1809,1534.11 1899.13,1624.24 J8.13
  Bottom Layer w10: v1(279,1583) 618.42,1583 655,1546.42 v1(655,1496) ; v1(1586,1264.42) 1584.5,1262.92 1584.5,481.92 1619.12,447.31 1619.12,315.31 J11.55@1664,270.42
NetC9_1: C9.1 C10.1 D1.A D2.K J5.1 U1.10 U1.11 U1.12 | length 834.7
  Top Layer w15: U1.12 U1.11
  Top Layer w100: 367,2805.37 367,2569 303,2505 303,2371 383,2291 624,2291
NetC12_2: C12.2 U1.9 | length 79
  Top Layer w10: C12.2@650,2429.42 650,2399.42 660.93,2388.49 U1.9
NetL1_1: L1.1 U1.1 U1.2 U1.3 | length 126.5
  Top Layer w15: L1.1@840.48,2314.42 L1.1@840.48,2388.42
  Top Layer w50: U1.2@788,2314.42 L1.1@840.48,2314.42
NetR5_1: R5.1 R7.2 U1.5 | length 405.3
  Top Layer w10: U1.5 748.53,2455.11 761.07,2467.66 R7.2@761.07,2542.35 ; R7.2@759,2542.35 R7.2 759,2555 784.5,2580.5 860.5,2580.5 880,2561 R5.1
NetR22_1: R22.1 U2.3 | length 86
  Top Layer w10: R22.1 1438,316.42 1445.18,323.61 U2.3
NetR23_1: R23.1 U2.2 | length 106.2
  Top Layer w10: R23.1 1385,295.92 1385,323.42 1398,336.42 1412,336.42 1419.59,344.01 U2.2
NetR24_1: R24.1 U2.1 | length 139.8
  Top Layer w10: R24.1 1329,363.42 1343,377.42 U2.1
RPI-RX: J6.2 J8.10 J11.31 J100.2 R10.1 R10.2 | length 1829.1
  Top Layer w8: J11.31@1664,1470.42 1721.5,1527.92 1721.5,1704.92 1749,1732.42 1824,1732.42 1874,1782.42 1946.4,1782.42 J8.10
  Top Layer w12: v1(838,1694) 838.26,1694.26 J100.2 J6.2@838.26,1913.42 ; v1(841,1508.42) R10.2 R10.1 1626,1508.42 J11.31@1664,1470.42
  Bottom Layer w12: v1(838,1694) 838,1513.42 v1@838.26,1513.16
RPI-TX: J6.3 J8.8 J11.29 J100.3 R11.1 R11.2 | length 1827
  Top Layer w8: J11.29@1664,1570.42 1707,1613.42 1707,1795.42 1739.5,1827.92 1781.6,1827.92 1846.34,1892.66 1956.63,1892.66 J8.8
  Top Layer w10: J6.3@759.52,1913.42 J100.3 759.52,1630.48 846,1544 1405,1544 1429.42,1568.42 R11.1 1463,1570.42 J11.29@1664,1570.42
RPI_CTS: J7.2 J8.36 J11.33 J101.2 R13.1 R13.2 | length 3641.6
  Top Layer w8: J7.2@287.08,659.42 287.08,1135.5 369,1217.42 R13.2 R13.1 888,1217.42 904,1233.42 ; v1(1296,404.42) 1314,422.42 1793,422.42 1853,482.42 1929,482.42 1981.73,535.16 J8.36
  Top Layer w10: 904,1233.42 1298,1233.42 v1(1299,1232.42) ; v1(1293,1384) 1296.08,1380.92 1664,1380.92 J11.33
  Bottom Layer w10: v1(1296,404.42) v1@1296,1384
RPI_RTS: J7.6 J8.11 J11.35 J101.6 R4.2 R12.1 R12.2 | length 2235.7
  Top Layer w8: J11.35 1664,1279.09 1707.5,1322.59 1707.5,1487.92 1747.5,1527.92 1781.6,1527.92 1806.5,1552.82 1806.5,1576.93 1850,1620.43 1850,1686.02 J8.11
  Top Layer w10: J7.6@602.04,659.42 J101.6@602.04,798.16 ; J101.6 603.34,981.34 747,1125 R4.2 R12.2 R12.1 877,1160.42 919,1202.42 1354.58,1202.42 v1(1355,1202) ; v1(1355,1344) 1356.92,1345.92 1605.8,1345.92 1655.71,1296.02 J11.35@1655.71,1285.71
  Bottom Layer w10: v1(1355,1202) v1(1355,1344)
RPI_SCL: J8.5 J10.4 J11.7 R29.1 R33.1 R33.2 | length 1824.3
  Top Layer w10: J10.4 1006,2738 1106,2638 1106,2489 1117.58,2477.42 R33.2 R33.1 1198,2471.28 1520.28,2471.28 1595,2546 1595,2608.42 J11.7 1715,2626.42 1715,2153.92 1744.92,2124 1797.42,2124 1886.27,2035.16 J8.5
RPI_SDA: J8.3 J10.3 J11.5 R30.1 R34.1 R34.2 | length 2036.4
  Top Layer w10: J10.3 862.26,2814.26 880,2832 951.14,2832 1141,2642.14 R30.1 1141,2532.42 R34.2 R34.1 1446.42,2531.42 1664,2749 J11.5 1673.58,2777.42 1726,2725 1810,2725 1840,2695 1840,2194.29 J8.3
  Top Layer w25: J10.3@862.26,2690.74 J10.3
SKY_ADC-M1_RING: J7.9 J101.9 R17.1 | length 389
  Top Layer w10: J101.9 838.26,659.42 872,625.68 R17.1
SKY_DIO2: J7.8 J101.8 R14.1 | length 290.3
  Top Layer w10: J101.8 763.34,663.24 759.52,659.42 817.5,601.44 R14.1
SKY_DIO3: J7.7 J101.7 R15.1 | length 409
  Top Layer w10: J101.7 680.78,838 680.78,659.42 680.78,651.64 763,569.42 R15.1
SKY_NRESET_RAW: J6.5 J100.5 Q2.3 | length 418.6
  Top Layer w12: J6.5@602.04,1913.42 J100.5 650.22,1664.31 Q2.3
SKY_ONOFF: J7.10 J101.10 Q1.3 | length 290.2
  Top Layer w10: J7.10@917,659.42 J101.10@917,798.16 ; J101.10 963.94,798.16 992.1,826.32 1057.58,826.32 Q1.3
SKY_USB_N: J4.2 J100.8 | length 751.4
  Top Layer w8: J4.2@115,1309.67 272,1309.67 274.4,1309.67 ccw(c274.4,1315.27) 280,1315.27 280,1323.07 cw(c285.6,1323.07) 285.6,1328.67 290.4,1328.67 cw(c290.4,1323.07) 296,1323.07 296,1315.27 ccw(c301.6,1315.27) 301.6,1309.67 303,1309.67 383.25,1309.67 397.69,1324.11 397.69,1513.31 352,1559 352,1680 375,1703 J100.8@375,1730
SKY_USB_P: J4.3 J100.7 | length 751.7
  Top Layer w8: J4.3@115,1294.67 389.46,1294.67 412.69,1317.9 412.69,1519.52 367,1565.21 367,1673.79 390.21,1697 427,1697
SKY_VUSB: J6.6
VCC_3V3: C13.1 J7.4 J8.1 J8.17 J9.2 J10.2 J11.8 J11.20 J11.32 J11.44 J101.4 R1.2 R6.2 R9.2 R22.2 R23.2 R24.2 R25.2 R26.2 R27.2 R29.2 R30.2 U2.8 | length 1208.6
  Top Layer w15: R6.2 v1(785,2143.42) ; v1(971,1077) 991.42,1077 R1.2 ; v1(1265.78,622.64) 1394,622.64 1394,646.42 1378,662.42 R27.2 R25.2 1378,767 ; v1(1279,236.42) R24.2 R23.2 R22.2 ; v1(1334,767) 1378,767 ; R26.2 1378,767
  Top Layer w25: J101.4 443.34,663.64 J7.4 ; v1@764,2647 764,2667 J10.2@786,2689 ; J10.2 783.52,2683.48 800,2667 v1(800,2650) ; v1(1198.16,2329.84) R9.2 ; R30.2 1211.36,2567.64 1247.36,2567.64 v1(1250,2565) ; v1@1270,2650 1270,2662 1283,2675 J9.2@1283,2779 ; J9.2@1295.99,2676.27 1310,2662.26 1308,2660.26 v1(1308,2650) ; R29.2 1491,2533 v1(1507,2549)
  other v1: 764,2650 1272,2650
VCC_4V0: C1.1 C2.1 C3.1 C11.1 J6.1 J100.1 L1.2 R5.2 U1.7 U1.14 | length 2029.6
  Top Layer w10: U1.14 709.16,2194.84 731.86,2172.14 837.28,2172.14 840,2169.42 903,2169.42 921,2187.42 C11.1@921,2233.61 ; U1.7 709.16,2469.43 678.19,2500.4 678.19,2570 704.69,2596.5 991.5,2596.5 R5.2@1025.52,2562.48 ; J100.1 922.58,1669.88 922.58,1730 C3.1 995,1903.54 C2.1@1004.88,1913.42 ; J6.1@917,1913.42 C2.1@1004.88,1913.42 ; C11.1 C11.1@921,2233.61 ; C1.1@1007.88,2076.42 1007.88,2146.72 941.18,2213.42 ; C1.1 C2.1 C2.1@1004.88,1913.42 ; R5.2 R5.2@1025.52,2562.48 ; C11.1@921,2233.61 941.18,2213.42 ; 941.18,2213.42 976,2213.42 1025.52,2262.94 R5.2@1025.52,2562.48
VCC_5V0_HAT: D1.K J8.2 J8.4 J11.4 J11.56 | length 2783
  Top Layer w50: J11.56 1764,271.66 2043.66,271.66 2065,293 2065,2069.29 J8.4 J8.2
  Top Layer w100: D1.K@430,2451 500,2521 500,2920
  other v1: 500,2900 475,2925 525,2925 500,2950
VCC_SKY_VUSB: C5.1 C6.1 J4.1 J100.6 | length 793.6
  Top Layer w30: J4.1@124,1356.42 179.42,1356.42 234.24,1411.24 C6.1 317.82,1411.24 v1(319,1412.42) ; J100.6 522,1740 533,1729 533,1421.42 v1(524,1412.42)
  Bottom Layer w30: v1(319,1412.42) v1(524,1412.42)
pads on no net: Fiducial1.Fiducial Fiducial2.Fiducial Fiducial3.Fiducial Fiducial4.Fiducial Fiducial5.Fiducial Fiducial6.Fiducial J4.0 J4.4 J5.2 J6.7 J6.8 J8.19 J8.21 J8.23 J8.24 J8.35 J8.37 J8.38 J8.40 J11.12 J11.16 J11.17 J11.19 J11.21 J11.23 J11.24 J11.28 J11.36 J11.39 J11.40 J11.41 J11.43 J11.48 J11.52 J11.53 J11.57 J11.59

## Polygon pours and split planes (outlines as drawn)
VCC_4V0 on Top Layer "T-4v0" (solid, remove dead copper, pour order 4): 942.48,1700.91 1004,1762.42 1004,1792.42 1004,1817.42 1049,1862.42 1049,2448.48 884,2201.54 884,1725.42 901,1620 913.14,1699.93 933,1634
GND on Top Layer "T-GND" (solid, remove dead copper, pour order 6): 159,3037.42 -6.01,3037.42 ccw(c-6.02,2957.44) -86,2957.42 -86,162.42 ccw(c39,162.42) 39,37.42 1989,37.42 ccw(c1989,137.42) 2089,137.42 2089,2957.42 ccw(c2009,2957.42) 2009,3037.42
GND on Bottom Layer "B-GND" (solid, remove dead copper, pour order 5): 159,3037.42 -6.01,3037.42 ccw(c-6.02,2957.44) -86,2957.42 -86,162.42 ccw(c39,162.42) 39,37.42 1989,37.42 ccw(c1989,137.42) 2089,137.42 2089,2957.42 ccw(c2009,2957.42) 2009,3037.42
GND on Internal Plane 1 (split plane): 2006.05,3022.38 2007.15,3022.44
GND on Internal Plane 1 (split plane): 2005.89,3018.49 2014.23,3021.95 2019.67,3021.14 2026.39,3019.46 2032.91,3017.12 2039.18,3014.16 2045.12,3010.6 2050.68,3006.47 2055.82,3001.82 2060.47,2996.68 2064.6,2991.12 2068.16,2985.17 2071.13,2978.91 2073.46,2972.39 2075.14,2965.66 2076.16,2958.81 2076.4,2953.89 2072.49,2953.89 2075.22,2947.31 2076.44,2947.47 2076.44,121.73 2076.48,121 2072.6,121 2073.61,118.58 2073.03,117.18 2072.49,115.89 2074.72,115.89 2076.06,112.66 2075.25,107.22 2073.57,100.5 2071.24,93.98 2068.27,87.71 2064.71,81.77 2060.58,76.2 2055.93,71.07 2050.79,66.42 2045.23,62.29 2039.29,58.73 2033.02,55.76 2026.5,53.43 2019.78,51.75 2012.92,50.73 2006.61,50.42 2006,50.45 0,50.45 -0.61,50.42 -6.92,50.73 -13.78,51.75 -20.5,53.43 -27.02,55.76 -33.29,58.73 -39.23,62.29 -44.79,66.42 -49.93,71.07 -54.58,76.2 -58.71,81.77 -62.27,87.71 -65.24,93.98 -67.57,100.5 -69.25,107.22 -70.06,112.66 -66.6,121 -70.12,121 -70.03,122.52 -70.11,123.89 -66.49,123.89 -70.44,133.4 -70.44,2951.22 -70.47,2951.89 -66.58,2951.89 -70.04,2960.23 -69.23,2965.66 -67.55,2972.39 -65.22,2978.91 -62.25,2985.17 -58.69,2991.12 -54.56,2996.68 -49.91,3001.82 -44.77,3006.47 -39.21,3010.6 -33.27,3014.16 -27,3017.12 -20.48,3019.46 -13.76,3021.14 -8.32,3021.95 0.02,3018.49 0.02,3022.37 0.76,3022.32 2005.15,3022.32 2005.89,3022.37
VCC_5V0_HAT on Internal Plane 2 (split plane): 2005.89,3018.49 2014.23,3021.95 2019.67,3021.14 2026.39,3019.46 2032.91,3017.12 2039.18,3014.16 2045.12,3010.6 2050.68,3006.47 2055.82,3001.82 2060.47,2996.68 2064.6,2991.12 2068.16,2985.17 2071.13,2978.91 2073.46,2972.39 2075.14,2965.66 2076.16,2958.81 2076.4,2953.89 2072.49,2953.89 2075.22,2947.31 2076.44,2947.47 2076.44,121.73 2076.48,121 2072.6,121 2073.61,118.58 2073.03,117.18 2072.49,115.89 2074.72,115.89 2076.06,112.66 2075.25,107.22 2073.57,100.5 2071.24,93.98 2068.27,87.71 2064.71,81.77 2060.58,76.2 2055.93,71.07 2050.79,66.42 2045.23,62.29 2039.29,58.73 2033.02,55.76 2026.5,53.43 2019.78,51.75 2012.92,50.73 2006.61,50.42 2006,50.45 1746.56,50.45 1746.56,337.42 1746.56,366.8 1931.88,552.12 1933.44,554.02 1934.6,556.19 1935.32,558.55 1935.56,561 1935.56,2198.95 1936.44,2200.02 1937.6,2202.19 1938.32,2204.55 1938.56,2207 1938.32,2209.45 1937.6,2211.81 1936.44,2213.98 1936.09,2214.41 1936.09,2271.58 1935.74,2274.19 1934.73,2276.62 1933.13,2278.71 1923.95,2287.89 1923.9,2288.45 1923.18,2290.81 1922.02,2292.98 1920.46,2294.88 1918.55,2296.44 1916.38,2297.6 1914.03,2298.32 1911.58,2298.56 1863.2,2298.56 1810.56,2351.2 1810.56,2698 1810.32,2700.45 1809.6,2702.81 1808.44,2704.98 1806.88,2706.88 1716.88,2796.88 1714.98,2798.44 1712.81,2799.6 1710.45,2800.32 1708,2800.56 434.56,2800.56 434.56,3022.32 2005.15,3022.32 2005.89,3022.37
VCC_3V3 on Internal Plane 2 (split plane): 0.76,3022.32 409.44,3022.32 409.44,2788 409.68,2785.55 410.4,2783.19 411.56,2781.02 413.12,2779.12 415.02,2777.56 417.19,2776.4 419.55,2775.68 422,2775.44 1702.8,2775.44 1785.44,2692.8 1785.44,2346 1785.68,2343.55 1786.4,2341.19 1787.56,2339.02 1789.12,2337.12 1849.12,2277.12 1851.02,2275.56 1853.19,2274.4 1855.55,2273.68 1858,2273.44 1909.87,2273.44 1915.91,2267.4 1915.91,2214.68 1914.12,2212.88 1912.56,2210.98 1911.4,2208.81 1910.68,2206.45 1910.44,2204 1910.44,566.2 1725.12,380.88 1723.56,378.98 1722.4,376.81 1721.68,374.45 1721.44,372 1721.44,337.42 1721.44,50.45 0,50.45 -0.61,50.42 -6.92,50.73 -13.78,51.75 -20.5,53.43 -27.02,55.76 -33.29,58.73 -39.23,62.29 -44.79,66.42 -49.93,71.07 -54.58,76.2 -58.71,81.77 -62.27,87.71 -65.24,93.98 -67.57,100.5 -69.25,107.22 -70.06,112.66 -66.6,121 -70.12,121 -70.03,122.52 -70.11,123.89 -66.49,123.89 -70.44,133.4 -70.44,2951.22 -70.47,2951.89 -66.58,2951.89 -70.04,2960.23 -69.23,2965.66 -67.55,2972.39 -65.22,2978.91 -62.25,2985.17 -58.69,2991.12 -54.56,2996.68 -49.91,3001.82 -44.77,3006.47 -39.21,3010.6 -33.27,3014.16 -27,3017.12 -20.48,3019.46 -13.76,3021.14 -8.32,3021.95 0.02,3018.49 0.02,3022.37

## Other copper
Top Layer:
  rectangle net NetC9_1: 624,2293 674,2340
  region net VCC_3V3: 800,2679 768,2679 768,2650 800,2650
  region net VCC_3V3: 1308,2670 1279,2670 1279,2650 1308,2650
  pour cut-out: 410.82,858.24 333.3,935.76 333.3,968.48 290.48,968.48 288,966
  pour cut-out: 696,863 890,863 915,838
  pour cut-out: 634,1003 676,961 676,934
  pour cut-out: 944.78,1608.22 989,1564 989,1554.22 987,1554.22 978,1545.22
  pour cut-out: 1308,2599.22 1290.78,2582 1261,2582
  pour cut-out: 369.84,2868.36 448.36,2868.36 449,2869 442,2876 442,2893
  pour cut-out: 1764,2677.42 1664,2577.42 1654,2587.42 1654,2602
  pour cut-out: 1930.87,1966.89 1974.53,1966.89 1979,1962.42 1974.17,1957.6 1938,1957.6
  pour cut-out: 1962.46,1623.51 1974.26,1623.5 2030.87,1566.89 2023.47,1566.89 2013.82,1557.25
  pour cut-out: 1664,2032.54 1764,2032.54 1764,2057.42
  pour cut-out: 1664,2322.31 1764,2322.31 1764,2292.42 1769,2287.42
  pour cut-out: 1702.87,2454.98 1702.87,2391.29 1699,2387.42
  pour cut-out: 1619.12,1677.42 1619.12,1877.42 1668.88,1877.42
  pour cut-out: 1619.75,1472.6 1619.75,1386.67 1634,1372.42
  pour cut-out: 1695.74,780.83 1695.74,594.16 1668.96,567.38
  pour cut-out: 1793,406.11 1883.3,406.11 1899.13,390.27
  pour cut-out: 1619.12,377.42 1708.88,377.42 1709,377.54 1709,452.42 1619,452.42
  pour cut-out: 1806,811.11 1861.87,811.11 1876.69,796.29
  pour cut-out: 2044.02,935.16 2044.02,1237.41 2029,1252.42 2014,1237.42 2014,1137.42
  pour cut-out: 2044.02,1535.16 2044.02,1435.16 2041.29,1432.42 2019,1432.42
  pour cut-out: 2044.02,1535.16 2044.02,1435.16 2041.29,1432.42 2009,1432.42 2009,1517.42
  pour cut-out: 1619.42,1179.72 1619.42,1307.84 1644,1332.42
  pour cut-out: 562.27,1817.73 545,1835 545,1888.13 582,1878
  pour cut-out: 840.48,2271.05 887.53,2224 891,2224 891,2237 903,2249 871,2281 852,2281
  pour cut-out: 1508.19,2257.42 1508.19,2284.81 1445.69,2347.31
  pour cut-out: 1054,2342 1118,2342 1118,2363.26
  pour cut-out: 509,2347 509,2447 479.12,2447 474.12,2452
Bottom Layer:
  pour cut-out: 1708.44,574.03 1708.88,573.58 1708.88,277.42 1657,277.42 1652,282.42
  pour cut-out: 2044.02,1235.16 2044.02,935.16 1999.13,935.16
  pour cut-out: 2044.02,1435.16 2044.02,1535.16 1999.13,1535.16 1899.13,1635.16 1894,1630.02 1894,1627.42
  pour cut-out: 1999.13,1735.16 1899.13,1635.16 1891.87,1642.42 1889,1642.42
  pour cut-out: 1944.02,1935.16 1944.02,2234.77 1943.63,2235.16 1940.9,2232.42 1884,2232.42
  pour cut-out: 1764,1522.31 1664,1522.31 1664,1492.42
  pour cut-out: 1664,2132.54 1644.83,2132.54 ccw(c1644.83,2089.04) 1601.33,2089.04 1601.33,2165.81
Internal Plane 2 (plane layer: these items are gaps in the copper):
  lines w20: 1911.58,2286 1926,2271.58 1926,2207
  lines w25: 620,3071.42 422,3071.42 422,2788 1708,2788 1798,2698 1798,2346 1858,2286 1911.58,2286 ; 1691,18.42 1731.42,18.42 1734,21 1734,337.42 1734,372 1923,561 1923,2204 1926,2207

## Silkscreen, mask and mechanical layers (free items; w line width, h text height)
Top Overlay:
  drawing of 3863 lines, arcs and shapes, not listed
  text "5V" at 403,2591 h80
  text "PCB: 1001503 REVA" at 594,132.42 h30
Bottom Overlay:
  text "1" at 1604,2957.42 h45
  text "2" at 1859,2957.42 h45
  text "2" at 2014,2317.42 h45
  text "1" at 1914,2312.42 h45
Mechanical 1:
  circle w20: c917,1719.42 r12
  lines w5: -118.11,121 ccw(c0,121) 0,2.89 2006,2.89 ccw(c2006,121) 2124.11,121 ; -118.09,2951.89 cw(c0.02,2951.89) 0.02,3070 ; -118,123.89 -118,2955.89 ; -3,3069.89 2005.89,3069.89 ; 1879.45,2215.47 1918.82,2254.84 ; 1879.45,2254.84 1918.82,2215.47 ; 1929.45,1265.47 1968.82,1304.84 ; 1929.45,1304.84 1968.82,1265.47 ; 2005.89,3070 cw(c2005.89,2951.89) 2124,2951.89 ; 2124,115.89 2124,2953.89
  lines w7: -98,715.49 -98,1854.42 1237,1854.42 1237,715.49 -98,715.49
Drill Drawing:
  drawing of 556 lines, arcs and shapes, not listed
  text "Layer" at -49,9072 h60
  text "Name" at 360.91,9072 h60
  text "Material" at 1400.62,9072 h60
  text "Thickness" at 2260.39,9072 h60
  text "Constant" at 2910.22,9072 h60
  text "Board Layer Stack" at 3480.08,9072 h60
  text "1" at -49,8952 h60
  text "Top Overlay" at 360.91,8952 h60
  text "2" at -49,8832 h60
  text "Top Solder" at 360.91,8832 h60
  text "Solder Resist" at 1400.62,8832 h60
  text "0.40mil" at 2260.39,8832 h60
  text "3.5" at 2910.22,8832 h60
  text "3" at -49,8712 h60
  text "Top Layer" at 360.91,8712 h60
  text "Copper" at 1400.62,8712 h60
  text "1.37mil" at 2260.39,8712 h60
  text "4" at -49,8592 h60
  text "Dielectric 1" at 360.91,8592 h60
  text "FR-4" at 1400.62,8592 h60
  text "6.70mil" at 2260.39,8592 h60
  text "4.6" at 2910.22,8592 h60
  text "5" at -49,8472 h60
  text "Internal Plane 1" at 360.91,8472 h60
  text "Copper" at 1400.62,8472 h60
  text "1.37mil" at 2260.39,8472 h60
  text "6" at -49,8352 h60
  text "Dielectric 3" at 360.91,8352 h60
  text "43.00mil" at 2260.39,8352 h60
  text "4.6" at 2910.22,8352 h60
  text "7" at -49,8232 h60
  text "Internal Plane 2" at 360.91,8232 h60
  text "Copper" at 1400.62,8232 h60
  text "1.37mil" at 2260.39,8232 h60
  text "8" at -49,8112 h60
  text "Dielectric 2" at 360.91,8112 h60
  text "6.70mil" at 2260.39,8112 h60
  text "4.6" at 2910.22,8112 h60
  text "9" at -49,7992 h60
  text "Bottom Layer" at 360.91,7992 h60
  text "Copper" at 1400.62,7992 h60
  text "1.37mil" at 2260.39,7992 h60
  text "10" at -49,7872 h60
  text "Bottom Solder" at 360.91,7872 h60
  text "Solder Resist" at 1400.62,7872 h60
  text "0.40mil" at 2260.39,7872 h60
  text "3.5" at 2910.22,7872 h60
  text "11" at -49,7752 h60
  text "Bottom Overlay" at 360.91,7752 h60
  text "Symbol" at -23,7378 h72
  text "Hit Count" at 482.88,7378 h72
  text "Finished Hole Size" at 1180.69,7378 h72
  text "Plated" at 2526.29,7378 h72
  text "Hole Type" at 3032.17,7378 h72
  text "1" at 482.88,7228 h60
  text "39.37mil (1.000mm)" at 1180.69,7228 h60
  text "PTH" at 2526.29,7228 h60
  text "Slot" at 3032.17,7228 h60
  text "2" at 482.88,7078 h60
  text "35.43mil (0.900mm)" at 1180.69,7078 h60
  text "NPTH" at 2526.29,7078 h60
  text "Round" at 3032.17,7078 h60
  text "2" at 482.88,6928 h60
  text "39.37mil (1.000mm)" at 1180.69,6928 h60
  text "PTH" at 2526.29,6928 h60
  text "Slot" at 3032.17,6928 h60
  text "4" at 482.88,6778 h60
  text "110.00mil (2.794mm)" at 1180.69,6778 h60
  text "NPTH" at 2526.29,6778 h60
  text "Round" at 3032.17,6778 h60
  text "8" at 482.88,6628 h60
  text "65.00mil (1.651mm)" at 1180.69,6628 h60
  text "PTH" at 2526.29,6628 h60
  text "Round" at 3032.17,6628 h60
  text "20" at 482.88,6478 h60
  text "31.50mil (0.800mm)" at 1180.69,6478 h60
  text "PTH" at 2526.29,6478 h60
  text "Round" at 3032.17,6478 h60
  text "100" at 482.88,6328 h60
  text "40.00mil (1.016mm)" at 1180.69,6328 h60
  text "PTH" at 2526.29,6328 h60
  text "Round" at 3032.17,6328 h60
  text "202" at 482.88,6178 h60
  text "15.00mil (0.381mm)" at 1180.69,6178 h60
  text "PTH" at 2526.29,6178 h60
  text "Round" at 3032.17,6178 h60
  text "339 Total" at 482.88,6028 h60
  text "NOTES:" at -113.01,5856.27 h56.25
  text "1. BOARD IS A 5x1 ARRAY. SEE PANEL ARTWORK LAYER FOR PANEL DETAIL." at -113.01,5750.27 h56.25
  text "2. BOARD TO BE SCORED AT DESIGNATED LINES. SCORING TO BE 30 DEG." at -113.01,5636.12 h56.25
  text "3. BOARD TO USE Tg 170C OR GREATER" at -113.01,5527.27 h56.25
  text "4. BOARD THICKNESS TOLERANCE +/- 10%" at -113.01,5407.84 h56.25
  text "5) BOARD TO USE GREEN SOLDER MASK" at -113.01,5293.7 h56.25
  text "6) BOARD TO USE WHITE SILK SCREEN" at -113.01,5179.55 h56.25
  text "7) MIN HOLE WALL THICKNESS 1 mil" at -113.01,5065.41 h56.25
  text "8) BOARD TO USE ENIG SURFACE FINISH" at -113.01,4951.27 h56.25
  text "9) COPPER LAYERS TO BE 1OZ COPPER" at -113.01,4842.27 h56.25
  text "FIDUCIAL" at 241,3672 h45
  text "FIDUCIAL" at 10856,3666 h45
  text "Scrap Rail" at 1269,3233 h60
  text "Copy Artwork" at 2977,1084 h45
  text "Copy Artwork" at 5289,1084 h45
  text "Copy Artwork" at 7601,1084 h45
  text "Copy Artwork" at 9913,1084 h45
  text "Cutout" at 2178,1069 h45 r90
  text "Cutout" at 4490,1069 h45 r90
  text "Cutout" at 6802,1069 h45 r90
  text "Cutout" at 9114,1069 h45 r90
  text "Scrap Rail" at 3089,-228 h60
  text "FIDUCIAL" at 290,-551 h45

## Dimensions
10984,3248 to 11369,3448 on Drill Drawing
11009,3220 to 11509,3109.78 on Drill Drawing
-121,3501 to 11509,3460 on Drill Drawing
-121,3448 to 2126,3470 on Drill Drawing
-57,3067 to -55,0 on Drill Drawing
-121,3448 to -118,-376 on Drill Drawing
